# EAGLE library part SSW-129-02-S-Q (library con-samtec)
THROUGH-HOLE .025" SQ POST SOCKET Source: Samtec SSW.pdf
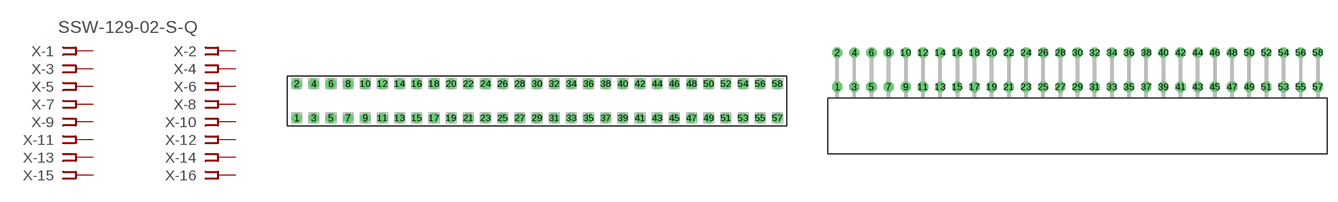
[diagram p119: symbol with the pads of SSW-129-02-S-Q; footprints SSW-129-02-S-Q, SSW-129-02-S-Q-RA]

Designator prefix X; gates -1=FPINV -2=FPIN -3=FPIN -4=FPIN -5=FPIN -6=FPIN -7=FPIN -8=FPIN -9=FPIN -10=FPIN -11=FPIN -12=FPIN -13=FPIN -14=FPIN -15=FPIN -16=FPIN -17=FPIN -18=FPIN -19=FPIN -20=FPIN -21=FPIN -22=FPIN -23=FPIN -24=FPIN -25=FPIN -26=FPIN -27=FPIN -28=FPIN -29=FPIN -30=FPIN -31=FPIN -32=FPIN -33=FPIN -34=FPIN -35=FPIN -36=FPIN -37=FPIN -38=FPIN -39=FPIN -40=FPIN -41=FPIN -42=FPIN -43=FPIN -44=FPIN -45=FPIN -46=FPIN -47=FPIN -48=FPIN -49=FPIN -50=FPIN -51=FPIN -52=FPIN -53=FPIN -54=FPIN -55=FPIN -56=FPIN -57=FPIN -58=FPIN

## SSW-129-02-S-Q (OC_FARNELL: unknown; OC_NEWARK: unknown)  [SSW-129-02-S-Q]
1  -1:1  pas
2  -2:1  pas
3  -3:1  pas
4  -4:1  pas
5  -5:1  pas
6  -6:1  pas
7  -7:1  pas
8  -8:1  pas
9  -9:1  pas
10  -10:1  pas
11  -11:1  pas
12  -12:1  pas
13  -13:1  pas
14  -14:1  pas
15  -15:1  pas
16  -16:1  pas
17  -17:1  pas
18  -18:1  pas
19  -19:1  pas
20  -20:1  pas
21  -21:1  pas
22  -22:1  pas
23  -23:1  pas
24  -24:1  pas
25  -25:1  pas
26  -26:1  pas
27  -27:1  pas
28  -28:1  pas
29  -29:1  pas
30  -30:1  pas
31  -31:1  pas
32  -32:1  pas
33  -33:1  pas
34  -34:1  pas
35  -35:1  pas
36  -36:1  pas
37  -37:1  pas
38  -38:1  pas
39  -39:1  pas
40  -40:1  pas
41  -41:1  pas
42  -42:1  pas
43  -43:1  pas
44  -44:1  pas
45  -45:1  pas
46  -46:1  pas
47  -47:1  pas
48  -48:1  pas
49  -49:1  pas
50  -50:1  pas
51  -51:1  pas
52  -52:1  pas
53  -53:1  pas
54  -54:1  pas
55  -55:1  pas
56  -56:1  pas
57  -57:1  pas
58  -58:1  pas

## SSW-129-02-S-QRA (OC_FARNELL: unknown; OC_NEWARK: unknown)  [SSW-129-02-S-Q-RA]
Pads as for SSW-129-02-S-Q

## Footprint SSW-129-02-S-Q (pad centres in mm)
THROUGH-HOLE .025" SQ POST SOCKET Source: Samtec SSW.pdf
drill 1 pad 1.5 octagon: 1 -35.56,-2.54; 2 -35.56,2.54; 3 -33.02,-2.54; 4 -33.02,2.54; 5 -30.48,-2.54; 6 -30.48,2.54; 7 -27.94,-2.54; 8 -27.94,2.54; 9 -25.4,-2.54; 10 -25.4,2.54; 11 -22.86,-2.54; 12 -22.86,2.54; 13 -20.32,-2.54; 14 -20.32,2.54; 15 -17.78,-2.54; 16 -17.78,2.54; 17 -15.24,-2.54; 18 -15.24,2.54; 19 -12.7,-2.54; 20 -12.7,2.54; 21 -10.16,-2.54; 22 -10.16,2.54; 23 -7.62,-2.54; 24 -7.62,2.54; 25 -5.08,-2.54; 26 -5.08,2.54; 27 -2.54,-2.54; 28 -2.54,2.54; 29 0,-2.54; 30 0,2.54; 31 2.54,-2.54; 32 2.54,2.54; 33 5.08,-2.54; 34 5.08,2.54; 35 7.62,-2.54; 36 7.62,2.54; 37 10.16,-2.54; 38 10.16,2.54; 39 12.7,-2.54; 40 12.7,2.54; 41 15.24,-2.54; 42 15.24,2.54; 43 17.78,-2.54; 44 17.78,2.54; 45 20.32,-2.54; 46 20.32,2.54; 47 22.86,-2.54; 48 22.86,2.54; 49 25.4,-2.54; 50 25.4,2.54; 51 27.94,-2.54; 52 27.94,2.54; 53 30.48,-2.54; 54 30.48,2.54; 55 33.02,-2.54; 56 33.02,2.54; 57 35.56,-2.54; 58 35.56,2.54

## Footprint SSW-129-02-S-Q-RA (pad centres in mm)
THROUGH-HOLE .025" SQ POST SOCKET Source: Samtec SSW.pdf
drill 1 pad 1.5 octagon: 1 -35.56,1.524; 2 -35.56,6.604; 3 -33.02,1.524; 4 -33.02,6.604; 5 -30.48,1.524; 6 -30.48,6.604; 7 -27.94,1.524; 8 -27.94,6.604; 9 -25.4,1.524; 10 -25.4,6.604; 11 -22.86,1.524; 12 -22.86,6.604; 13 -20.32,1.524; 14 -20.32,6.604; 15 -17.78,1.524; 16 -17.78,6.604; 17 -15.24,1.524; 18 -15.24,6.604; 19 -12.7,1.524; 20 -12.7,6.604; 21 -10.16,1.524; 22 -10.16,6.604; 23 -7.62,1.524; 24 -7.62,6.604; 25 -5.08,1.524; 26 -5.08,6.604; 27 -2.54,1.524; 28 -2.54,6.604; 29 0,1.524; 30 0,6.604; 31 2.54,1.524; 32 2.54,6.604; 33 5.08,1.524; 34 5.08,6.604; 35 7.62,1.524; 36 7.62,6.604; 37 10.16,1.524; 38 10.16,6.604; 39 12.7,1.524; 40 12.7,6.604; 41 15.24,1.524; 42 15.24,6.604; 43 17.78,1.524; 44 17.78,6.604; 45 20.32,1.524; 46 20.32,6.604; 47 22.86,1.524; 48 22.86,6.604; 49 25.4,1.524; 50 25.4,6.604; 51 27.94,1.524; 52 27.94,6.604; 53 30.48,1.524; 54 30.48,6.604; 55 33.02,1.524; 56 33.02,6.604; 57 35.56,1.524; 58 35.56,6.604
